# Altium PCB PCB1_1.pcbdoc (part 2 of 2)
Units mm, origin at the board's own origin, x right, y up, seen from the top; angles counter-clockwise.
Board outline 93.4 x 134 mm, 2 copper layers (Top Layer, Bottom Layer); 92 components, 71 nets, 349 pads, 191 vias.
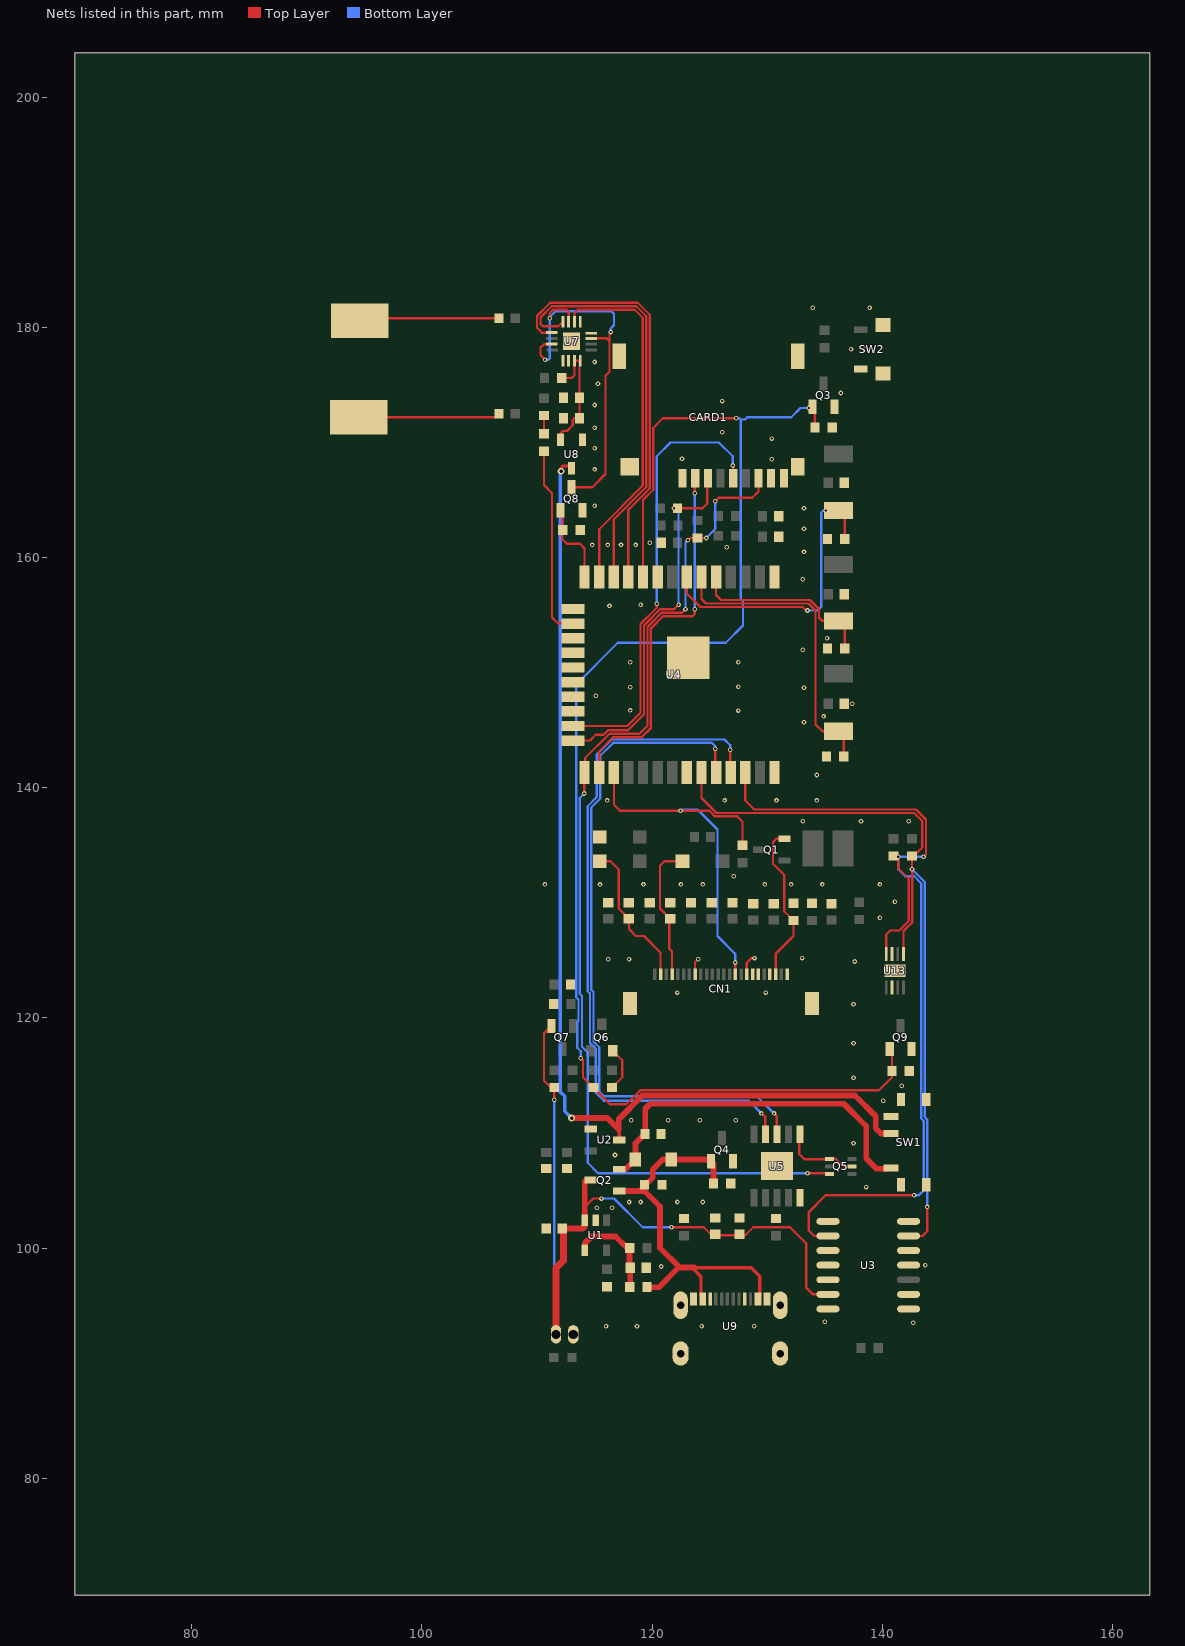
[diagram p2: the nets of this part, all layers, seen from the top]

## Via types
v1: diameter 0.4, hole 0.2, Top Layer to Bottom Layer, 188 vias
v2: diameter 0.6, hole 0.3, Top Layer to Bottom Layer, 3 vias

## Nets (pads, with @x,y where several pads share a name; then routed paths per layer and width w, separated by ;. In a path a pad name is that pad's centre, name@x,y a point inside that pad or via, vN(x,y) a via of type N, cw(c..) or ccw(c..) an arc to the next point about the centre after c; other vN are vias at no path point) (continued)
GND: C1.1 C2.1 C3.1 C4.1 C5.1 C6.1 C7.1 C8.1 C9.1 C11.1 C12.2 C13.2 C15.1 C16.1 C22.1 C23.1 C24.1 C25.1 C26.1 C27.1 C28.2 C29.2 C30.2 C33.1 C34.1 C35.1 CN1.8 CN1.17 D1.1 P1.1 Q3.2 Q4.2 Q6.2 Q8.2 Q9.2 R1.1 R2.1 R4.2 R27.2 R28.1 R29.1 R30.2 R31.1 R41.2 R43.2 R45.1 R52.2 R53.2 R54.2 R57.2 SW2.2 U1.2 U2.1 U3.7 U3.11 U4.1 U4.15 U4.38 U4.39 U8.1 U9.17 U9.18 U9.19 U9.20 U9.A1 U9.A12 U9.B1 U9.B12 | length 7.2
  Top Layer w0.2: R41.2@116.5,113.947 117.4,114.847 117.4,116.327 Q6.2@116.577,117.15 ; CN1.8@123.736,123.789 123.736,124.836 v1(124,125.1) ; CN1.17@128.235,123.789 128.235,124.8 128.635,125.2 v1(128.9,125.2)
  other v1: 116,93.2 118.69,93.2 124.3,93.2 128.868,93.2 142.704,93.514 135,93.6 120.8,98.4 143.753,98.514 115.2,103.5 116.529,103.5 118,104 119,104 122.2,104 124.411,104 138.6,105.3 116.776,108.091 137.5,109.1 118.2,111.1 121.4,111.1 124.135,111.1 127.266,111.1 140.1,112.8 141.7,114.1 137.5,114.8 137.5,117.8 137.5,121.189 122.2,122.2 129.877,122.2 137.6,124.9 116.2,125.1 118,125.1 133.048,125.2 139.8,128.713 141.1,130.1 110.663,131.6 115.477,131.6 119.255,131.6 122.504,131.6 124.4,131.6 129.8,131.6 132.1,131.6 134.8,131.6 139.8,131.6 127.1,132.3 133.1,137.1 138.152,137.1 142.302,137.1 130.813,138.899 116.1,138.9 126.3,138.9 134.3,138.9 134.3,141.112 133.2,145.7 134.9,146.2 118.1,146.719 127.5,146.705 137.4,147.3 115.1,148 133.2,148.7 118.1,148.744 127.5,148.775 118.1,150.9 127.5,150.9 133.1,152 135.205,152.994 116.3,155.8 119,155.9 133.1,158.112 133.2,160.494 126.5,160.9 114.8,161.1 116.138,161.1 117.3,161.1 118.565,161.1 119.8,161.3 133.2,162.5 133.2,164.3 115,164.5 115,167.66 130.4,168.552 122.6,168.6 115,169.5 130.4,170.343 126.1,170.9 115,171.281 115,173.258 126.1,173.6 136.4,174.3 115.3,175.1 115,177 137.292,178.1 138.525,178.1 133.959,181.7 138.9,181.7
I2S-SCK: U4.12 U7.16 | length 36.6
  Top Layer w0.2: U7.16@112.252,180.5 111.852,180.1 110.502,180.1 110.302,180.3 110.302,180.875 111.273,181.846 118.627,181.846 119.498,180.975 119.498,166.138 116.671,163.31 U4.12@116.671,158.315
I2S-SDA: U4.11 U7.1 | length 36.8
  Top Layer w0.2: U7.1@111.3,179.55 110.415,179.55 110,179.965 110,181 111.148,182.148 118.752,182.148 119.8,181.1 119.8,166.012 117.941,164.153 U4.11@117.941,158.315
I2S-WS: U4.13 U7.14 | length 31.1
  Top Layer w0.2: U7.14@113.252,180.6 113.252,181.248 113.547,181.544 118.502,181.544 119.196,180.85 119.196,166.263 115.401,162.468 U4.13@115.401,158.315
IO0: CARD1.7 Q5.6 R58.2 U4.25 | length 92.9
  Top Layer w0.2: v1(114.1,139.5) 114.1,141.284 U4.25@114.131,141.314 114.2,141.384 114.2,142.6 116.3,144.7 116.592,144.7 116.502,144.702 118.9,144.702 119.594,145.396 119.594,153.975 120.823,155.204 122.604,155.204 v1(122.9,155.5) ; v1(123.1,161.5) 123.307,161.707 124.159,161.707 124.166,161.7 v1(124.7,161.7) ; v1(125.5,164.9) 125.8,165.2 128.701,165.2 129.25,165.749 CARD1.7@129.25,166.9 ; v1(133.5,106.5) 135.36,106.5 Q5.6@135.41,106.45
  Bottom Layer w0.2: v1(114.1,139.5) 113.704,139.104 113.704,122.096 113.904,121.896 113.904,117.496 114.4,117 114.4,107.408 115.308,106.5 v1(133.5,106.5) ; v1(122.9,155.5) 122.9,161.3 v1(123.1,161.5) ; v1(124.7,161.7) 125.5,162.5 v1(125.5,164.9)
IO2: CARD1.3 R59.2 U4.24 | length 32.4
  Top Layer w0.2: U4.24@113.131,144.099 114.6,144.099 115.101,144.6 115.773,144.6 116.175,145.002 116.2,145.002 ; 116.2,145.004 117.9,145.004 119.292,146.396 119.292,154.1 120.698,155.506 121.906,155.506 v1(122.3,155.9) ; v1(121.9,164.3) 122.299,164.3 122.312,164.287 124.387,164.287 124.8,164.7 124.8,166.85 CARD1.3@124.85,166.9
  Bottom Layer w0.2: v1(121.9,164.3) 122.3,163.9 v1(122.3,155.9)
IO4: CARD1.2 U4.26 | length 32
  Top Layer w0.2: U4.26@115.401,141.314 115.401,143.174 116.627,144.4 119.1,144.4 119.896,145.196 119.896,153.85 120.948,154.902 123.503,154.902 123.7,155.1 v1(123.7,155.5) ; v1(123.7,165.6) 123.7,166.85 CARD1.2@123.75,166.9
  Bottom Layer w0.2: v1(123.7,155.5) v1(123.7,165.6)
IO12: Q8.1 R45.2 U4.14 | length 7.3
  Top Layer w0.2: Q8.1@112.05,164.1 112.247,163.903 R45.2@112.247,162.4 112.2,162.353 112.2,161.6 112.6,161.2 113.731,161.2 114.131,160.8 U4.14@114.131,158.315
IO13: R46.2 U4.16 | length 16.8
  Top Layer w0.2: R46.2@110.6,169.247 110.6,166.3 111.3,165.6 111.3,154.8 111.8,154.3 113.09,154.3 U4.16@113.131,154.259
IO15: CARD1.5 U4.23 | length 38.7
  Top Layer w0.2: U4.23@113.131,145.369 117.838,145.369 118.99,146.521 118.99,154.226 120.4,155.636 v1(120.4,156) ; v1(127,168) 127.05,167.95 CARD1.5@127.05,166.9
  Bottom Layer w0.2: v1(120.4,156) 120.4,168.8 121.6,170 125.8,170 127,168.8 v1(127,168)
IO16: CN1.15 R50.2 U4.27 | length 33.7
  Top Layer w0.2: U4.27@116.671,141.314 116.686,141.299 116.686,138.514 117.186,138.014 v1(122.464,138.014) 124.959,138.014 125.461,137.512 127.4,137.512 127.859,137.054 R50.2@127.859,134.993 ; CN1.15@127.235,123.789 v1(127.235,124.814)
  Bottom Layer w0.2: v1@122.586,138.014 122.683,138.112 123.942,138.112 125.69,136.365 125.69,127.11 127.235,125.565 v1(127.235,124.814)
IO21: R35.2 U3.13 U4.33 U13.1 | length 68.3
  Top Layer w0.2: U4.33@124.291,141.314 124.291,139.109 125.586,137.814 128.54,137.814 128.542,137.812 142.788,137.812 143.486,137.114 143.486,134.814 142.732,134.061 R35.2@142.586,134.061 v1(142.586,132.914) 142.6,132.9 142.6,128.3 141.85,127.55 U13.1@141.85,125.554 ; U3.13@142.286,101.054 143.5,101.054 143.9,101.454 v1(143.9,103.575)
  Bottom Layer w0.2: v1(142.586,132.914) 143.686,131.814 143.686,111.387 143.9,111.173 v1(143.9,103.575)
IO22: R34.2 U3.2 U4.36 U13.4 | length 79.4
  Top Layer w0.2: U4.36@128.101,141.314 128.101,138.899 128.886,138.114 142.923,138.114 143.802,137.236 143.802,134.23 v1(143.586,134.014) ; U3.2@135.286,101.054 134.1,101.054 133.6,101.554 133.6,103.1 135.1,104.6 v1(142.765,104.6) ; U13.4@140.35,125.554 140.35,127.25 140.7,127.6 141.473,127.6 142.298,128.425 142.298,132.1 ; R34.2@141,134.047 141.032,134.014 v1(141.386,134.014) 141.386,133.014 142.298,132.102
  Bottom Layer w0.2: v1(142.765,104.6) 143.2,104.6 143.598,104.998 ; v1(143.586,134.014) v1(141.386,134.014) 141.386,132.914 142,132.3 142.773,132.3 143.384,131.689 143.384,111.262 143.598,111.048 143.598,105
IO25: Q3.1 Q9.1 R27.1 R39.1 R57.1 U4.10 | length 130.3
  Top Layer w0.2: v1(113.8,116.5) 114,116.3 114,114.847 R39.1@114.9,113.947 116.347,112.5 117.761,112.5 118.963,113.702 139.7,113.702 140.847,114.849 R57.1@140.847,115.4 140.847,117.103 Q9.1@140.65,117.3 ; U4.10@119.211,158.315 119.211,164.996 120.102,165.887 120.102,171.267 120.935,172.1 v1(127.3,172.1) ; v1(133.6,173) 133.85,173 Q3.1@133.95,173.1 134.147,172.903 R27.1@134.147,171.3
  Bottom Layer w0.2: v1(113.8,116.5) 113.8,117.1 113.5,117.4 113.5,119.615 113.6,119.715 113.6,121.6 113.402,121.798 113.402,148.975 117.025,152.598 126.398,152.598 127.9,154.1 127.9,156.2 127.7,156.4 127.7,171.997 ; v1(127.3,172.1) 127.597,172.1 127.7,171.997 ; v1(133.6,173) 132.9,173 132.097,172.197 128.273,172.197 128.073,171.997 127.7,171.997
IO33: U4.9
IO34: pad.1@136.2,144.9 R52.1 U4.6 | length 26.8
  Top Layer w0.2: U4.6@124.291,158.315 124.291,156.409 124.686,156.014 133.586,156.014 134.2,155.4 134.2,145.5 134.8,144.9 pad.1@136.2,144.9 136.653,144.447 R52.1@136.653,142.7
IO35: pad.1@136.2,164.1 R54.1 U4.7 | length 26.4
  Top Layer w0.2: U4.7@123.021,158.315 123.021,156.882 124.202,155.7 133.1,155.7 133.4,155.4 v1(133.5,155.4) ; v1(135.1,164.1) pad.1@136.2,164.1 136.753,163.547 R54.1@136.753,161.6
  Bottom Layer w0.2: v1(133.5,155.4) 134.4,155.4 134.7,155.7 134.7,163.9 134.9,164.1 v1(135.1,164.1)
IO39: pad.1@136.2,154.5 R53.1 U4.5 | length 16.2
  Top Layer w0.2: U4.5@125.561,158.315 125.561,156.739 125.984,156.316 133.711,156.316 134.502,155.525 134.502,154.8 134.802,154.5 pad.1@136.2,154.5 136.753,153.947 R53.1@136.753,152.1
OUTN: pad.1@94.5,172.2 U11.2 | length 12.1
  Top Layer w0.2: pad.1@94.714,172.187 94.727,172.2 106.4,172.2 U11.2@106.7,172.5
OUTP: pad.1@94.6,180.6 U12.2 | length 12.2
  Top Layer w0.2: pad.1@94.6,180.6 94.8,180.8 U12.2@106.7,180.8
PREVGH: C6.2 CN1.4 D3.1 | length 12.1
  Top Layer w0.2: CN1.4@121.736,123.789 121.736,125.764 121.486,126.014 121.486,128.514 C6.2@121.586,128.614 120.686,129.514 120.686,133.214 121.086,133.614 D3.1@122.651,133.614
PREVGL: C8.2 CN1.2 D2.2 | length 13
  Top Layer w0.2: D2.2@115.451,133.614 116.386,133.614 117.1,132.9 117.1,129.5 C8.2@117.986,128.614 117.986,127.714 118.586,127.114 119.286,127.114 120.736,125.664 CN1.2@120.736,123.789
RESE: CN1.22 Q1.2 R2.2 | length 14
  Top Layer w0.2: CN1.22@130.736,123.789 130.736,125.564 132.286,127.114 R2.2@132.286,128.461 131.486,129.261 131.486,132.414 130.5,133.4 130.5,135.264 130.8,135.564 Q1.2@131.487,135.564
RTS: Q5.2 Q5.4 U5.6 | length 7.2
  Top Layer w0.2: U5.6@132.843,109.881 132.799,109.837 132.799,108.161 133.249,107.711 135.249,107.711 Q5.4@135.349,107.811 ; Q5.2@137.39,107.1 136.6,107.1 135.95,107.75 Q5.4@135.628,107.75 ; Q5.4@135.349,107.811 Q5.4@135.41,107.75 Q5.4@135.628,107.75 ; Q5.4@135.349,107.811 135.567,107.811 Q5.4@135.628,107.75
RXD: U4.34 U5.8 | length 60.6
  Top Layer w0.2: v1(125.5,143.4) 125.5,141.375 U4.34@125.561,141.314 ; v1(130.6,111.7) 130.843,111.457 U5.8@130.843,109.881
  Bottom Layer w0.2: v1(125.5,143.4) 125.5,143.6 125.202,143.898 116.625,143.898 115.502,142.775 115.502,139.069 114.708,138.275 114.708,122.446 114.908,122.246 114.908,117.946 115.404,117.45 115.404,113.623 115.827,113.2 129.1,113.2 v1(130.6,111.7)
SOUND-DB: R44.1 R46.1 | length 1.6
  Top Layer w0.2: R46.1@110.6,170.753 R44.1@110.6,172.347
SUND-3V3: C33.2 C34.2 R56.1 U7.7 U7.8 U8.2 | length 11
  Top Layer w0.2: U8.2@112.05,170.235 112.05,170.8 112.25,171 112.598,171 113.1,171.502 113.1,171.956 113.244,172.1 C33.2@113.7,172.1 C34.2@113.7,173.9 113.7,177.048 U7.8@113.752,177.1 U7.7@113.252,177.1 113.252,175.849 113.003,175.6 R56.1@112.153,175.6
SUND-GND: Q8.3 U7.3 U7.11 U7.15 | length 34.8
  Top Layer w0.2: v1(110.7,177.2) 110.302,177.598 110.302,178.25 110.6,178.548 U7.3@111.3,178.548 ; v1(111.1,180.8) 111.1,181.245 111.399,181.544 112.6,181.544 112.752,181.392 U7.15@112.752,180.5 ; Q8.3@113,166.1 114.8,166.1 115.957,167.257 115.957,175.807 116.293,176.144 116.293,178.829 ; U7.11@114.7,179.05 116.073,179.05 116.293,178.829 ; v1(116.4,179.6) 116.293,179.494 116.293,178.829
  Bottom Layer w0.2: v1(110.7,177.2) 111,177.2 111.1,177.3 v1(111.1,180.8) 111.1,180.898 111.6,181.398 116.475,181.398 116.696,181.177 116.696,180.2 116.4,179.904 v1(116.4,179.6)
SWITCHIN: SW1.2 U2.3 U8.3 | length 90.5
  Top Layer w0.3: v2(112.1,167.5) 112.1,167.765 112.293,167.958 112.807,167.958 U8.3@113,167.765 ; U2.3@117.135,109.4 117.135,110.26
  Top Layer w0.5: v2(113,111.3) 116.095,111.3 117.1,110.295 117.1,111.2 119.15,113.25 137.637,113.25 139.437,111.45 139.437,110.4 139.887,109.95 SW1.2@140.675,109.95
  Bottom Layer w0.3: v2@112,167.4 112,113.588 112.4,113.188 112.4,111.9 v2(113,111.3)
SWITCHOUT: C22.2 D4.1 Q2.2 SW1.3 | length 32
  Top Layer w0.5: Q2.2@117.135,106.85 117.7,106.85 D4.1@118.55,107.7 118.55,109.1 119.364,109.914 C22.2@119.386,109.914 ; C22.2@119.4,109.929 119.4,112.1 119.848,112.548 136.652,112.548 138.6,110.6 138.6,107.8 139.5,106.9 140.625,106.9 SW1.3@140.675,106.95
TXD: U4.35 U5.9 | length 61.9
  Top Layer w0.2: v1(126.8,143.3) 126.8,141.345 U4.35@126.831,141.314 ; v1(129.5,111.7) 129.525,111.7 129.843,111.382 U5.9@129.843,109.881
  Bottom Layer w0.2: v1(126.8,143.3) 126.8,143.7 126.3,144.2 116.5,144.2 115.2,142.9 115.2,139.194 114.406,138.4 114.406,122.321 114.606,122.121 114.606,117.821 115.102,117.325 115.102,113.498 115.8,112.8 128.4,112.8 v1(129.5,111.7)
VBAT: C13.1 C23.2 C24.2 P1.2 Q2.3 Q7.2 R40.1 U1.3 U3.6 | length 71.6
  Top Layer w0.2: Q7.2@111.25,119.3 110.6,118.65 110.6,114.547 111.2,113.947 R40.1@111.5,113.947 v1(111.5,112.9) ; 114.15,103.565 114.885,104.3 v1(115.6,104.3) ; v1(121.686,101.814) 124.486,101.814 125.186,101.114 126.286,101.114 128.086,101.114 128.786,101.814 131.986,101.814 133.386,100.414 133.386,96.574 133.986,95.974 U3.6@135.286,95.974
  Top Layer w0.5: C13.1@112.2,101.7 114,101.7 114.15,101.85 U1.3@114.15,102.4 114.15,103.565 114.15,105.785 114.265,105.9 Q2.3@114.665,105.9
  Top Layer w0.6: P1.2@111.65,92.3 111.65,98.25 112.3,98.9 112.3,101.6 C13.1@112.2,101.7
  Bottom Layer w0.2: v1(111.5,112.9) 111.5,94.609 111.65,94.459 P1.2@111.65,92.5 ; v1(115.6,104.3) 116.7,104.3 119.186,101.814 v1(121.686,101.814)
VBUS: D4.2 Q2.1 Q4.1 R5.1 R28.2 R31.2 U9.A4 U9.A9 U9.B4 U9.B9 | length 35.2
  Top Layer w0.3: U9.A4@124.25,95.757 124.25,97.521 123.671,98.1 123.671,98.3 128.6,98.3 129.35,97.55 U9.A9@129.35,95.757
  Top Layer w0.5: Q2.1@117.135,104.95 118.897,104.95 ; R5.1@119.553,96.6 120.6,96.6 122.3,98.3 ; 123.671,98.3 122.4,98.3 120.686,100.014 120.686,103.614 119.35,104.95 118.897,104.95 ; R28.2@125.332,105.714 125.332,107.349 Q4.1@125.135,107.547 124.982,107.7 D4.2@121.65,107.7 120.932,107.7 120.047,106.814 120.047,106.1 118.897,104.95
VCC-R: C12.1 R3.1 R5.2 U1.4 | length 8.6
  Top Layer w0.5: U1.4@114.15,99.8 114.15,100.414 114.75,101.014 116.832,101.014 117.847,100 R3.1@118.047,100 118.047,98.353 C12.1@118.1,98.3 118.1,96.653 R5.2@118.047,96.6
"": CARD1.1 CARD1.8 CARD1.9 CARD1.10 CARD1.11 CARD1.12 CARD1.13 CN1.18 CN1.19 CN1.21 CN1.24 CN1.25 CN1.26 SW1.1 SW1.4 SW2.3 SW2.4 U3.1 U3.3 U3.4 U3.5 U3.8 U3.9 U3.12 U3.14 U4.17 U4.18 U4.19 U4.20 U4.21 U4.22 U4.32 U5.5 U5.11 U7.5 U7.6 U7.12 U7.13 U7.17 U9.A8 U9.B8 U13.3 U13.6 U13.9

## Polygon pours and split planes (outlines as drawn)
GND on Top Layer (solid, remove dead copper, pour order 0): 83.7,76.5 156.9,76.5 156.9,187.5 83.7,187.5
GND on Bottom Layer (solid, remove dead copper, pour order 1): 76.2,76.2 155.6,76.2 155.6,197.5 76.2,197.5

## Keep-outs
Board Outline Layer:
  lines w0.2 net "": 109.3,170.5 109.329,170.471 109.329,168.4 109.329,92.8 109.329,90.8 ccw(c110.803,90.876) 110.8,89.4 ; 109.329,170.5 90.931,170.5 90.931,182.4 139.1,182.4 cw(c138.925,180.625) 140.7,180.8 140.7,174.4 137.786,174.4 137.786,140.414 144.3,140.414 144.3,90.899 ; 110.803,89.4 116.2,89.4 142.9,89.4 ccw(c142.798,90.899) 144.3,90.9

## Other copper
Top Layer:
  drawing of 384 lines, arcs and shapes, not listed
Bottom Layer:
  region net VBAT: 111.55,93.589 111.3,93.133 112,93.133 111.75,93.589
  region net $1N5042: 125.7,97.132 125.65,97.34 125.45,97.34 125.4,97.132
  region net $1N5135: 128.736,97.347 128.686,97.554 128.486,97.554 128.436,97.347
  region net $1N5042: 125.7,97.132 125.65,97.34 125.45,97.34 125.4,97.132
  region net VBAT: 121.553,101.964 121.346,101.914 121.346,101.714 121.553,101.664
  region net VBAT: 115.732,104.15 115.94,104.2 115.94,104.4 115.732,104.45
  region net $1N5042: 122.636,99.982 122.784,99.774 123.067,99.774 122.936,99.982
  region net 3V3: 132.036,111.247 132.156,111.444 131.884,111.454 131.736,111.247
  region net DATA+: 126.7,96.947 126.65,97.154 126.45,97.154 126.4,96.947
  region net DATA+: 127.7,96.947 127.65,97.15 127.45,97.15 127.4,96.947
  region net $1N5135: 130.636,100.182 130.504,99.974 130.787,99.974 130.936,100.182
  region net $1N5135: 130.636,100.182 130.504,99.974 130.787,99.974 130.936,100.182
  region net $1N5135: 130.636,100.182 130.686,100.114 130.886,100.114 130.936,100.182
  region net DATA-: 127.936,97.583 128.125,97.74 128.093,97.99 127.897,97.88
  region net DATA-: 129.25,102.768 129.3,102.56 129.5,102.56 129.55,102.768
  region net DATA+: 128.636,103.182 128.686,102.974 128.886,102.974 128.936,103.182
  region net DIN: 129.236,139.682 129.286,139.474 129.486,139.474 129.536,139.682
  region net CS: 126.385,124.947 126.335,125.114 126.135,125.114 126.085,124.947
  region net CLK: 125.748,126.114 125.566,126.226 125.424,126.084 125.536,125.902
  region net IO16: 127.385,124.947 127.335,125.154 127.135,125.154 127.085,124.947
  region net BUSY: 127.936,125.347 127.886,125.497 127.686,125.497 127.636,125.347
  region net DC: 128.568,125.832 128.718,126.005 128.63,126.2 128.445,126.106
  region net DIN: 129.436,127.247 129.386,127.454 129.186,127.454 129.136,127.247
  region net CLK: 120.336,139.382 120.386,139.174 120.586,139.174 120.636,139.382
  region net CS: 119.046,139.682 119.096,139.474 119.296,139.474 119.346,139.682
  region net DC: 121.773,139.415 121.955,139.303 122.097,139.445 121.985,139.627
  region net IO22: 143.453,134.164 143.246,134.114 143.246,133.914 143.453,133.864
  region net IO22: 141.236,133.882 141.286,133.674 141.486,133.674 141.536,133.882
  region net IO22: 141.518,133.864 141.726,133.914 141.726,134.114 141.518,134.164
  region net VBAT: 111.35,112.768 111.4,112.56 111.6,112.56 111.65,112.768
  region net ADC-BAT: 113.25,114.532 113.2,114.74 113,114.74 112.95,114.532
  region net ADC-BAT: 112.95,120.468 113,120.26 113.2,120.26 113.25,120.468
  region net ADC-BAT: 113.25,120.732 113.2,120.94 113,120.94 112.95,120.732
  region net IO25: 113.95,116.632 113.9,116.84 113.7,116.84 113.65,116.632
  region net IO0: 133.368,106.65 133.16,106.6 133.16,106.4 133.368,106.35
  region net IO0: 113.9,139.513 113.789,139.33 113.93,139.189 114.113,139.3
  region net TXD: 129.513,111.9 129.33,112.011 129.189,111.87 129.3,111.688
  region net RXD: 130.613,111.9 130.43,112.011 130.289,111.87 130.4,111.688
  region net EN: 134.068,108.85 133.86,108.8 133.86,108.6 134.068,108.55
  region net RXD: 125.65,143.532 125.501,143.74 125.219,143.74 125.35,143.532
  region net TXD: 126.95,143.432 126.9,143.64 126.7,143.64 126.65,143.432
  region net EN: 128.187,156.6 128.37,156.489 128.511,156.63 128.4,156.813
  region net EN: 128.35,156.932 128.3,157.14 128.1,157.14 128.05,156.932
  region net ADC-BAT: 126.65,156.668 126.7,156.46 126.9,156.46 126.95,156.668
  region net CLK: 127.496,155.142 127.498,155.379 127.298,155.491 127.234,155.289
  region net IO4: 123.85,155.632 123.8,155.84 123.6,155.84 123.55,155.632
  region net 3V3: 135.532,147.25 135.606,147.3 135.606,147.5 135.532,147.55
  region net SWITCHIN: 113.019,111.599 112.745,111.767 112.533,111.555 112.701,111.281
  region net SWITCHIN: 111.822,167.388 111.85,167.048 112.15,166.941 112.246,167.238
  region net $2N1555: 115.932,178.35 116.14,178.4 116.14,178.6 115.932,178.65
  region net SUND-GND: 116.55,179.732 116.5,179.904 116.3,179.904 116.25,179.732
  region net 3V3: 136.568,91.55 136.36,91.5 136.36,91.3 136.568,91.25
  region net IO22: 142.897,104.45 143.105,104.5 143.105,104.7 142.897,104.75
  region net IO21: 144.05,103.707 144,103.915 143.8,103.915 143.75,103.707
  region net IO21: 142.573,132.715 142.755,132.603 142.897,132.745 142.785,132.927
  region net IO35: 133.632,155.25 133.84,155.3 133.84,155.5 133.632,155.55
  region net 3V3: 135.568,116.05 135.36,116 135.36,115.8 135.568,115.75
  region net DC: 126.55,122.168 126.6,121.96 126.8,121.96 126.85,122.168
  region net CLK: 127.05,162.968 127.1,162.76 127.3,162.76 127.35,162.968
  region net DIN: 125.65,160.968 125.7,160.76 125.9,160.76 125.95,160.968
  region net DIN: 126.013,153.8 125.871,153.871 125.729,153.729 125.8,153.588
  region net 3V3: 136.321,128.355 136.533,128.4 136.547,128.6 136.343,128.655
  region net 3V3: 137.668,128.65 137.46,128.6 137.46,128.4 137.668,128.35
  region net IO35: 134.968,164.25 134.76,164.101 134.771,163.829 134.968,163.95
  region net $1N1499: 117.65,101.468 117.7,101.26 117.9,101.26 117.95,101.468
  region net $1N1499: 117.95,92.032 117.9,92.24 117.7,92.24 117.65,92.032
  region net $2N1588: 115.632,177.35 115.84,177.4 115.84,177.6 115.632,177.65
  region net SUND-GND: 110.95,180.668 111,180.46 111.2,180.46 111.25,180.668
  region net SUND-GND: 111.292,180.857 111.386,181.042 111.193,181.132 111.019,180.983
  region net SUND-GND: 110.832,177.05 111,177.1 111,177.3 110.832,177.35
  region net $2N1555: 109.3,172.588 109.411,172.77 109.27,172.911 109.087,172.8
  region net $2N1588: 109.3,181.488 109.411,181.67 109.27,181.811 109.087,181.7
  region net 8025INT: 134,114.713 133.889,114.53 134.03,114.389 134.213,114.5
  region net 8025INT: 139.85,92.132 139.701,92.34 139.419,92.34 139.55,92.132
  region net 8025INT: 135.988,114.5 136.129,114.429 136.271,114.571 136.2,114.713
  region net 8025INT: 115.25,125.168 115.3,124.96 115.5,124.96 115.55,125.168
  region net DC: 138.75,126.468 138.8,126.26 139,126.26 139.05,126.468
  region net $4N231: 140.95,126.868 141,126.66 141.2,126.66 141.25,126.868
  region net $4N231: 140.95,126.868 141,126.66 141.2,126.66 141.25,126.868
  region net $4N231: 141.613,121 141.43,121.111 141.289,120.97 141.4,120.788
  region net 8025INT: 121.55,156.268 121.6,156.06 121.8,156.06 121.85,156.268
  region net 8025INT: 112.75,126.132 112.7,126.34 112.5,126.34 112.45,126.132
  region net IO4: 123.55,165.468 123.6,165.26 123.8,165.26 123.85,165.468
  region net IO2: 122.45,156.032 122.4,156.24 122.2,156.24 122.15,156.032
  region net IO2: 121.887,164.1 122.07,163.989 122.211,164.13 122.1,164.313
  region net IO0: 123.05,155.632 123,155.84 122.8,155.84 122.75,155.632
  region net IO15: 120.55,156.132 120.5,156.34 120.3,156.34 120.25,156.132
  region net IO15: 127.15,168.132 127.1,168.34 126.9,168.34 126.85,168.132
  region net IO0: 122.9,161.513 122.829,161.371 122.971,161.229 123.113,161.3
  region net IO0: 125.35,164.768 125.4,164.56 125.6,164.56 125.65,164.768
  region net IO0: 124.9,161.688 125.011,161.87 124.87,162.011 124.687,161.9
  region net EN: 134.85,177.668 134.9,177.46 135.1,177.46 135.15,177.668
  region net IO25: 133.468,173.15 133.26,173.1 133.26,172.9 133.468,172.85
  region net IO25: 127.432,171.95 127.597,172 127.597,172.2 127.432,172.25

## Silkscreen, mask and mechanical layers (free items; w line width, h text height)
Top Silkscreen Layer:
  text "68UH" at 102.799,180.466 h0.78
  text "10K" at 136.266,180.067 h0.78 r270
  text "MAX98357" at 103.363,178.466 h0.78
  text "SPEAKER" at 92.197,176.066 h0.78
  text "0R" at 108.268,175.166 h0.78
  text "10u" at 114.572,173.666 h0.78
  text "200K" at 106.499,173.466 h0.78
  text "CJ2302" at 127.531,172.866 h0.78
  text "68UH" at 102.844,172.166 h0.78
  text "1u" at 114.712,171.772 h0.78
  text "10K" at 129.134,170.666 h0.78
  text "6206" at 111.499,168.566 h0.78
  text "0R" at 110.166,168.432 h0.78 r270
  text "0.1u" at 132.038,165.966 h0.78
  text "2302" at 109.399,164.766 h0.78
  text "22U" at 129.31,164.766 h0.78
  text "10K" at 115.034,163.966 h0.78
  text "10K" at 117.71,163.866 h0.78
  text "10K" at 117.266,163.767 h0.78 r270
  text "I35" at 132.676,163.666 h0.78
  text "10K" at 115.034,162.466 h0.78
  text "10K" at 109.534,162.066 h0.78
  text "10K" at 132.41,161.266 h0.78
  text "10K" at 117.574,161.031 h0.78
  text "1U" at 115.182,161.006 h0.78
  text "0.1U" at 129.128,159.866 h0.78
  text "0.1u" at 132.138,156.466 h0.78
  text "I39" at 132.376,154.166 h0.78
  text "10K" at 132.341,151.666 h0.78
  text "0.1u" at 132.175,146.966 h0.78
  text "I34" at 132.41,144.566 h0.78
  text "10K" at 132.334,142.366 h0.78
  text "0.1u" at 123.352,138.198 h0.78
  text "10K" at 127.525,137.912 h0.78 r270
  text "0530" at 115.63,137.004 h0.78
  text "10uH" at 133.799,136.966 h0.78
  text "0530" at 122.899,136.866 h0.78
  text "2302" at 129.099,136.766 h0.78
  text ".47R" at 131.966,133.401 h0.78 r270
  text "0.1u" at 128.466,133.001 h0.78 r270
  text "0.1u" at 135.166,132.901 h0.78 r270
  text "10K" at 137.666,132.867 h0.78 r270
  text "10K" at 133.566,132.767 h0.78 r270
  text "10K" at 142.252,132.714 h0.78 r270
  text "10K" at 140.666,132.69 h0.78 r270
  text "1u" at 115.866,132.332 h0.78 r270
  text "1u" at 117.666,132.223 h0.78 r270
  text "1u" at 119.366,132.223 h0.78 r270
  text "1u" at 121.266,132.223 h0.78 r270
  text "1u" at 123.066,132.223 h0.78 r270
  text "1u" at 124.858,132.178 h0.78 r270
  text "1u" at 126.666,132.123 h0.78 r270
  text "1u" at 130.255,132.122 h0.78 r270
  text "22u" at 111.112,127.426 h0.78
  text "100K" at 110.799,126.166 h0.78
  text "CJ2301" at 109.331,124.966 h0.78
  text "S8050" at 113.865,124.966 h0.78
  text "GXHT30" at 134.731,123.666 h0.78
  text "CJ2302" at 135.331,117.866 h0.78
  text "1M" at 138.668,114.966 h0.78
  text "10K" at 114.503,113.074 h0.78 r270
  text "1M" at 116.166,113.032 h0.78 r270
  text "100K" at 111.166,113.017 h0.78 r270
  text "100K" at 112.666,113.008 h0.78 r270
  text "CH340K" at 128.731,111.466 h0.78
  text "10u" at 119.034,111.066 h0.78
  text "6206" at 115.551,110.908 h0.78 r270
  text "CJ2302" at 123.831,110.566 h0.78
  text "NPN" at 135.234,108.666 h0.78
  text "3401" at 115.582,107.308 h0.78 r270
  text "22u" at 110.466,105.841 h0.78 r270
  text "22u" at 112.266,105.841 h0.78 r270
  text "RX8025" at 136.331,104.266 h0.78
  text "1MR" at 125.034,103.766 h0.78
  text "4007" at 118.499,103.666 h0.78
  text "1M" at 119.468,102.566 h0.78
  text "10u" at 125.166,100.167 h0.78 r270
  text "0.1u" at 127.266,100.175 h0.78 r270
  text "5.1K" at 130.466,100.175 h0.78 r270
  text "5.1K" at 122.466,100.001 h0.78 r270
  text "10u" at 110.559,99.671 h0.78
  text "TP4055" at 109.931,98.066 h0.78
  text "1.66K" at 115.766,95.859 h0.78 r270
  text "1K" at 118.168,94.866 h0.78
  text "1uF" at 117.834,93.666 h0.78
  text "1R" at 118.068,92.466 h0.78
  text "10K" at 140.434,90.966 h0.78
  text "LED" at 113.91,90.166 h0.78
Bottom Silkscreen Layer:
  text "TF卡： /  CLK:   IO15 /  MISO:  IO0 /  MOSI:  IO2 /  CS:    IO04" at 121.77,169.725 h1.72
  text "Eink： /  CLK:   IO18 /  MISO:  IO19 /  MOSI:  IO23 /  CS:    IO05" at 133.695,169.575 h1.72
  text "按键： /  上:  IO35 /  中:  IO39 /  下:  IO34" at 121.895,156.892 h1.72
  text "其他： /  BAT:   IO36 /  WAKE:  IO25 /  AMP:   IO34 /  RX8025INT:IO32" at 133.12,156.828 h1.72
  text "I2C： /  SCL:  IO22 /  SDA:  IO21" at 133.195,146.766 h1.72
  text "I2S： /  SDA:  IO26 /  SCK:  IO27 /  WS:   IO14 /  WAKE: IO32 /  S-DB: IO13" at 121.745,144.503 h1.72
Mechanical Layer:
  lines w0.025 net "": 117.986,115.6 117.986,117.2 ccw(c120.986,117.2) 120.986,114.2 130.986,114.2 ccw(c130.986,117.2) 133.986,117.2 133.986,115.6 ccw(c130.986,115.6) 130.986,118.6 120.986,118.6 ccw(c120.986,115.6) 117.986,115.6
